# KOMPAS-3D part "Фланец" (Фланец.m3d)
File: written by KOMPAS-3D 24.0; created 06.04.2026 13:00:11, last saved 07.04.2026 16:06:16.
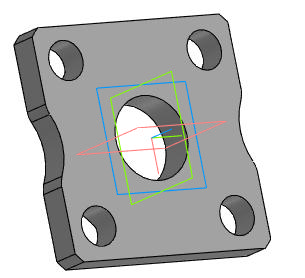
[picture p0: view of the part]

Document properties: Автор: R2D2; Полное имя файла: E:\Работа\Зайцев\Солянка\VSR1-13V-PED-F Клапан запорно-регулирующий DN.ru\DN40\исходные материалы\Фланец.m3d

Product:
- Component [standard]: (unnamed)  | qty 1  | Материал: ВЧ40 ГОСТ 7293-85 (density 7200 kg/m3); Масса: 1.96; additional columns: 40-16-01-2-B-ВЧ40-II-dв 49,5; Фланец; ГОСТ 33259-2015
- Part/product: Фланец
    Масса: 1.237185

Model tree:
1. Эскиз:6
2. Элемент выдавливания:6
3. Эскиз:7  (with: Ребро.Элемент выдавливания:6)
4. Элемент выдавливания:7
5. Зеркальный массив:2
6. Экземпляр ( 1 )
7. Экземпляр ( 2 )  (with: Элемент выдавливания:7)
8. Эскиз:8
9. Элемент выдавливания:8
     Расстояние 2 = 18
10. Скругление:2  (with: Ребро.Элемент выдавливания:8)
     Радиус = 10

Expressions: v520+20
Referenced files in C:\Program Files\ASCON\KOMPAS-3D v24\Libs\PolynomLib\DATA\vault\Methods\Kompas\3D\: PLib_Flange_GOST_33259_1401.m3d
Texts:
  BOSimple***Material:38d6725a-5efe-48e1-b177-a7817acb862a
  BOSimple***PART:763e3dbd-ceda-e15d-6080-7258d879ed5d***SHORTLOC:B6A6_23E38AE8DB154823[II;2;Круглый;40;16;49,5;0;ВЧ40 ГОСТ 7293-85]
  Ch34
  Плоскость XY.Начало координат
  Ось Z.Начало координат
  Plane ZX. Origin
  Плоскость ZX.Начало координат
